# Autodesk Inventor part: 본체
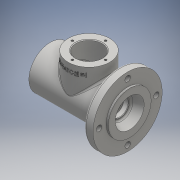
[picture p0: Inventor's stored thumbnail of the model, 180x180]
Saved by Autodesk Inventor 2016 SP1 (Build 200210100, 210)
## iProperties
Created: 2016-08
Part Number: 본체
Material: 일반
Document SubType Name: Modeling
Designer: basic
Density: 1 g/cm^3
Appearance: 기본값
Author: basic
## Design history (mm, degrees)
sketch "스케치1"
  geometry: L1 (57.5, 0)-(-57.5, 0); L2 (57.5, 0)-(57.5, 31); L3 (57.5, 31)-(-41.5, 31); L4 (-41.5, 31)-(-41.5, 50); L5 (-41.5, 50)-(-54.5, 50); L6 (-54.5, 50)-(-54.5, 31); L7 (-54.5, 31)-(-57.5, 31); L8 (-57.5, 31)-(-57.5, 0); L9 (57.5, 21)-(48.5, 21); L10 (48.5, 21)-(48.5, 24); L11 (48.5, 24)-(45.5, 24); L12 (45.5, 24)-(45.5, 20); L13 (45.5, 20)-(36.5, 20); L14 (36.5, 20)-(36.5, 17.5); L15 (36.5, 17.5)-(33.25, 17.5); L16 (33.25, 17.5)-(33.25, 18.5); L17 (33.25, 18.5)-(31.5, 18.5); L18 (31.5, 18.5)-(31.5, 17.5); L19 (31.5, 17.5)-(20.5, 17.5); L20 (20.5, 17.5)-(20.5, 26); L21 (20.5, 26)-(-17.5, 26); L22 (-17.5, 26)-(-17.5, 17.5); L23 (-17.5, 17.5)-(-28.5, 17.5); L24 (-28.5, 17.5)-(-28.5, 16.5); L25 (-28.5, 16.5)-(-33.5, 16.5); L26 (-33.5, 16.5)-(-33.5, 10); L27 (-33.5, 10)-(-36.2, 10); L28 (-36.2, 10)-(-36.2, 12.5); L29 (-36.2, 12.5)-(-42.8, 12.5); L30 (-42.8, 12.5)-(-43.5, 12.904); L31 (-43.5, 12.904)-(-43.5, 16); L32 (-43.5, 16)-(-57.5, 21); L33 (1.5, 26)-(1.5, 0); 2 further points
  constraints: 66 end point, 19 perpendicular, 8 vertical, 4 horizontal, 3 point on line, 2 midpoint, 1 coincident
  dimensions: "d0" = 115 distance of L1.start L1.end; "d1" = 100 diameter of L5 L1; "d2" = 62 diameter of L7 L1; "d3" = 13 distance of L4.end L5.end; "d4" = 3 distance of L6.end L7.end; "d5" = 62 diameter of L3 L1; "d6" = 3 distance of L10.end L11.end; "d7" = 40 diameter of L13 L1; "d9" = 12 distance between parallel lines of L2 L12; "d10" = 21 distance between parallel lines of L2 L14; "d11" = 42 diameter of L9 L1; "d12" = 48 diameter of L11 L1; "d13" = 26 distance from line of L1.start L18; "d14" = 35 diameter of L15 L1; "d15" = 35 diameter of L19 L1; "d16" = 1.75 distance of L16.end L17.end; "d17" = 37 diameter of L17 L1; "d18" = 52 diameter of L21 L1; "d19" = 38 distance of L20.end L21.end; "d41" = 60 distance between parallel lines of L18 L24; "d42" = 33 diameter of L25 L1; "d43" = 35 diameter of L23 L1; "d44" = 5 distance of L24.end L25.end; "d45" = 2.7 distance of L26.end L27.end; "d46" = 20 diameter of L27 L1; "d47" = 25 diameter of L29 L1; "d54" = 0.7 horizontal distance of L29.end L30.end; "d55" = 30 deg angle of L29 L30; "d56" = 32 diameter of L31.end L1; "d57" = 42 diameter of L32.end L1; "d58" = 7.3 distance between parallel lines of L31 L28; "d76" = 56 distance between parallel lines of L2 L33
revolve "회전1" sketch "스케치1" stored, may be unused: angle "d59" = 90 deg
node "작업 평면1"
sketch "스케치2"
  geometry: L1 (-57.5, 31)-(-57.5, -31) reference; C1 r 30 at (-1.5, 0); 1 further point
  constraints: 1 centre point, 1 horizontal alignment, 1 midpoint
  dimensions: "d61" = 60 diameter of C1; "d75" = 56 distance from line of C1.centre L1
extrude "돌출1" join sketch "스케치2" stored distance "d62" = 10; taper "d63" = 0 deg; dims "d88" = 41.5
hole "구멍1" diameter "d66" = 38; stored, may be unused: countersink angle "d70" = 90 deg, drill point angle "d72" = 0 deg; dims "d64" = 10, "d65" = 10, "d67" = 6, "d68" = 4, "d69" = 2, "d71" = 8
feature "스레드1" dims "d73" = 10, "d74" = 0
sketch "스케치4"
  geometry: L1 (0, 0)-(0, 24); C1 r 30 at (0, 0) reference; 2 further points
  constraints: 2 end point, 1 coincident, 1 vertical
  dimensions: "d77" = 24 distance of L1.start L1.end
hole "구멍2" sketch "스케치4" at (0, 24) diameter "d78" = 3.242; stored, may be unused: countersink angle "d82" = 90 deg, drill point angle "d84" = 118 deg; dims "d79" = 8, "d80" = 4, "d81" = 2, "d83" = 10
sketch "스케치5"
  geometry: L1 (0, 0)-(-41.5, 0); 1 further point
  constraints: 2 end point, 1 coincident, 1 horizontal
  dimensions: "d88" = 41.5 distance of L1.start L1.end
hole "구멍3" sketch "스케치5" at (-41.5, 0) diameter "d89" = 8; stored, may be unused: countersink angle "d93" = 90 deg, drill point angle "d95" = 0 deg; dims "d90" = 8, "d91" = 4, "d92" = 2, "d94" = 10
node "작업 평면2"
sketch "스케치6"
  geometry: L1 (-31.5, 49)-(28.5, 49) reference; L2 (-57.5, 31)-(-57.5, -31) reference; 2 further points
  constraints: 1 other
  dimensions: "d100" = 10 distance from line of L1 point (-1.5, 39); "d101" = 56 distance from line of L2 point (-1.5, 39)
feature "엠보싱1" sketch "스케치6" dims "d102" = 0.5, "d103" = 0
fillet "모깎기1" dims "d104" = 3
fillet "모깎기2" dims "d105" = 3
fillet "모깎기3" dims "d106" = 3
fillet "모깎기4" dims "d107" = 3
fillet "모깎기5" dims "d108" = 0.3
fillet "모깎기6" dims "d109" = 3
fillet "모깎기7" dims "d110" = 3
fillet "모깎기8" dims "d111" = 0.3
chamfer "모따기1" distance "d112" = 1; stored, may be unused: second distance "d113" = 2, angle "d114" = 45 deg
node "솔리드1"
pattern_circular "원형 패턴1" dims angle "d86" = 360 deg
pattern_circular "원형 패턴2" dims angle "d97" = 360 deg
other parameters: "d60" = 49, "d99" = -31
